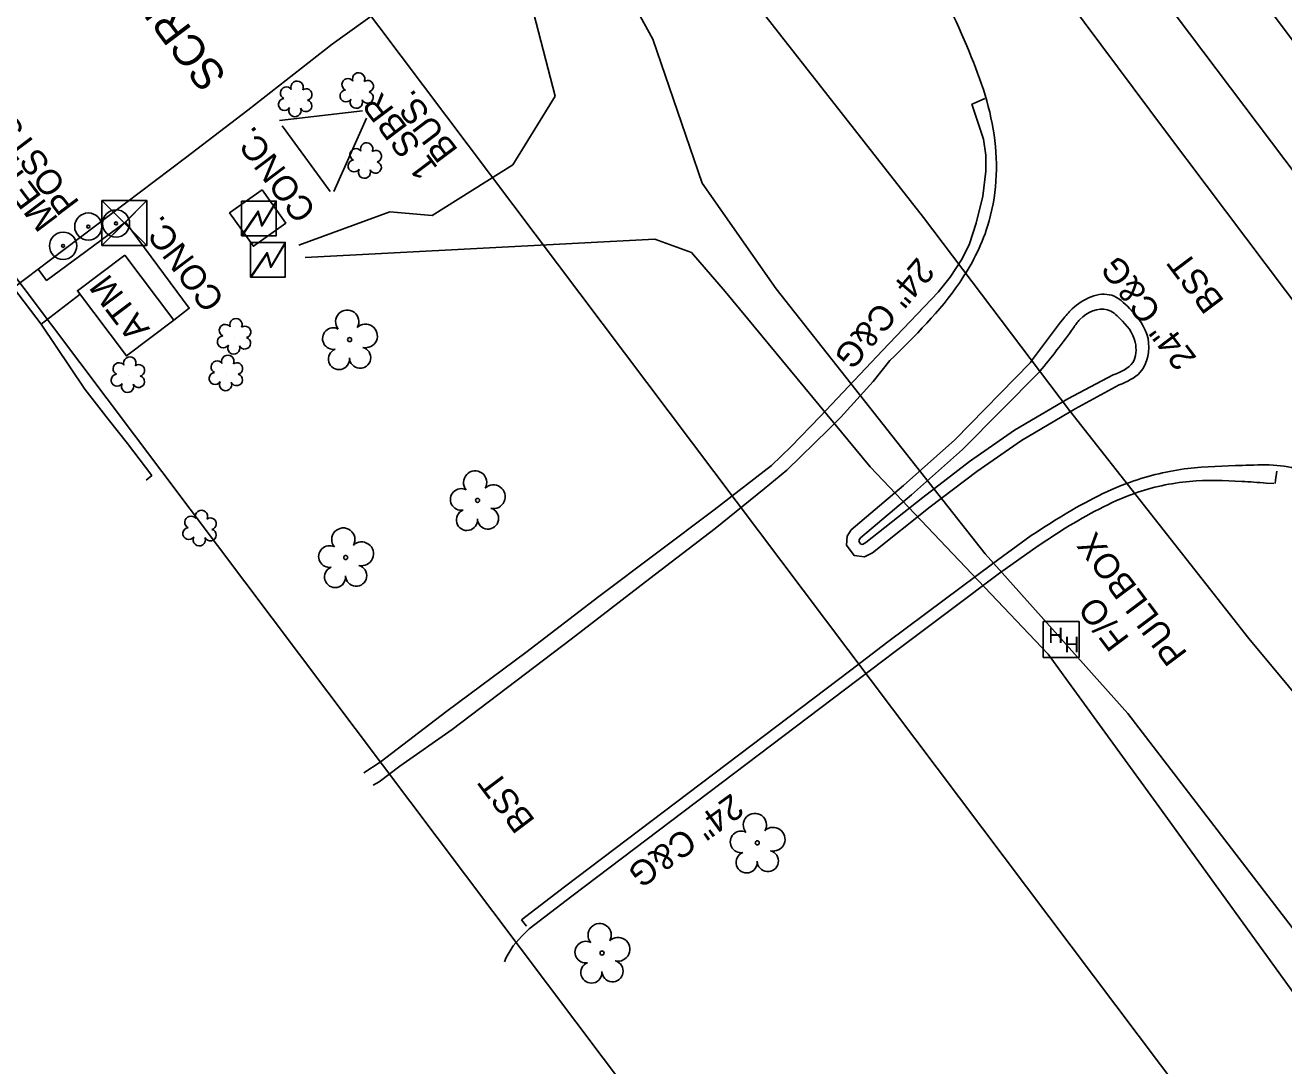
# Model space of a CAD drawing. Extents: x 1262092 to 1264624, y 774970 to 778314.
# Drawn here: x 1263925.8 to 1264127.3, y 775381.8 to 775548.3 of the extents above; entities that cross this region are included whole.
import ezdxf

# ---------------------------------------------------------------- set-up
doc = ezdxf.new("R2010")
doc.units = 0
for name, color, linetype in [('COGO Default Parcel', 7, 'Continuous'), ('CTL Vertical Benchmark CELL', 7, 'Continuous'), ('Exist Horizontal Alignment', 7, 'Continuous'), ('Exist Horizontal Alignment Station Label', 7, 'Continuous'), ('Exist Horizontal Alignment Tick Large', 7, 'Continuous'), ('Exist Horizontal Alignment Tick Small', 7, 'Continuous'), ('Exist Right of Way Line', 7, 'Continuous'), ('Exist Roads Curbs', 7, 'Continuous'), ('Exist Roads EOP', 7, 'Continuous'), ('Exist Roads EOP Other', 7, 'Continuous'), ('Exist Roads EOT', 7, 'Continuous'), ('Exist Structure Minor Drop Inlet Top Elevation', 7, 'Continuous'), ('Exist Utilities Power UG Cable SUE LOS B', 7, 'Continuous'), ('Exist Utilities Telephone Hand Hole CELL', 7, 'Continuous'), ('Exist Utilities Telephone Hand Hole Text', 7, 'Continuous'), ('Exist Utilities Telephone UG FO SUE LOS B', 7, 'Continuous'), ('Exist Utilities Water UG Line SUE LOS B', 7, 'Continuous'), ('Prop Horizontal Alignment', 7, 'Continuous'), ('Prop Horizontal Alignment Direction Label', 7, 'Continuous'), ('Prop Horizontal Alignment Station Label', 7, 'Continuous'), ('Prop Paved Shoulder', 7, 'Continuous'), ('Prop Superelevation Label', 7, 'Continuous'), ('Prop Terminator CELL', 7, 'Continuous'), ('Sheet Block Revision CELL', 7, 'Continuous'), ('Sheet Data Field CELL', 7, 'Continuous'), ('Sheet North Arrow Point CELL', 7, 'Continuous'), ('Sheet Plan CELL', 7, 'Continuous'), ('Sheet Sticker Incomplete CELL', 7, 'Continuous')]:
    doc.layers.add(name, color=color, linetype=linetype)

# ---------------------------------------------------------------- blocks, each defined once
blk = doc.blocks.new('CTL VERTICAL BENCHMARK')
at = {"layer": 'CTL Vertical Benchmark CELL'}
blk.add_line((0, 0), (0, 0), dxfattribs=at)
blk.add_lwpolyline([(-0.072, 0.07175), (0.07175, 0.07175), (0.07175, -0.072), (-0.072, -0.072)], close=True, dxfattribs=at)
for points in [[(0.07175, 0.07175), (-0.072, -0.072), (-0.000125, -0.000125), (0.07175, -0.072), (-0.072, 0.07175)], [(-0.000125, -0.000125), (0.07175, 0.07175), (-0.072, 0.07175), (-0.000125, -0.000125)], [(-0.000125, -0.000125), (-0.072, -0.072), (0.07175, -0.072), (-0.000125, -0.000125)]]:
    blk.add_lwpolyline(points, dxfattribs=at)

msp = doc.modelspace()

# ---------------------------------------------------------------- linework, layer by layer
at = {"layer": 'COGO Default Parcel'}
msp.add_line((1264304.64, 775002.74), (1263276.19, 776368.79), dxfattribs=at)
at = {"layer": 'Exist Horizontal Alignment'}
msp.add_line((1264460.35, 775084.79), (1262255.05, 778012.66), dxfattribs=at)
at = {"layer": 'Exist Horizontal Alignment Station Label'}
for p, q in [((1263966.49, 775533.11), (1263979.78, 775534.65)), ((1263980.41, 775533.49), (1263975.17, 775521.71)), ((1263974.62, 775521.75), (1263966.94, 775532.21))]:
    msp.add_line(p, q, dxfattribs=at)
at = {"layer": 'Exist Horizontal Alignment Tick Large'}
for p, q in [((1263978.93, 775537.71), (1263978.93, 775537.71)), ((1263969.08, 775536.37), (1263969.08, 775536.37)), ((1263980.22, 775526.51), (1263980.22, 775526.51)), ((1263959.29, 775498.37), (1263959.29, 775498.37)), ((1263942.29, 775492.22), (1263942.29, 775492.22)), ((1263957.98, 775492.51), (1263957.98, 775492.51)), ((1263953.77, 775467.68), (1263953.77, 775467.68))]:
    msp.add_line(p, q, dxfattribs=at)
for centre, radius, start, end in [((1263969.31, 775538.41), 0.99, 334.8391, 200.4717), ((1263977.45, 775538.84), 0.968, 35.8908, 245.4216), ((1263979.16, 775539.75), 0.99, 334.8391, 200.4717), ((1263980.6, 775538.58), 0.929, 284.4567, 126.0861), ((1263967.6, 775537.49), 0.968, 35.8908, 245.4216), ((1263970.75, 775537.24), 0.929, 284.4567, 126.0861), ((1263977.13, 775537.01), 0.955, 95.1099, 327.9534), ((1263980.57, 775536.78), 0.937, 204.9913, 73.4601), ((1263967.28, 775535.66), 0.955, 95.1099, 327.9534), ((1263968.95, 775534.68), 0.984, 151.2797, 21.387), ((1263970.72, 775535.44), 0.937, 204.9913, 73.4601), ((1263978.8, 775536.03), 0.984, 151.2797, 21.387), ((1263980.45, 775528.55), 0.99, 334.8391, 200.4717), ((1263978.74, 775527.64), 0.968, 35.8908, 245.4216), ((1263981.89, 775527.38), 0.929, 284.4567, 126.0861), ((1263978.42, 775525.81), 0.955, 95.1099, 327.9534), ((1263980.09, 775524.83), 0.984, 151.2797, 21.387), ((1263981.86, 775525.58), 0.937, 204.9913, 73.4601), ((1263959.52, 775500.41), 0.99, 334.8391, 200.4717), ((1263957.81, 775499.49), 0.968, 35.8908, 245.4216), ((1263960.97, 775499.24), 0.929, 284.4567, 126.0861), ((1263957.49, 775497.66), 0.955, 95.1099, 327.9534), ((1263959.17, 775496.68), 0.984, 151.2797, 21.387), ((1263960.93, 775497.44), 0.937, 204.9913, 73.4601), ((1263942.52, 775494.27), 0.99, 334.8391, 200.4717), ((1263956.5, 775493.64), 0.968, 35.8908, 245.4216), ((1263958.21, 775494.55), 0.99, 334.8391, 200.4717), ((1263940.81, 775493.35), 0.968, 35.8908, 245.4216), ((1263943.96, 775493.09), 0.929, 284.4567, 126.0861), ((1263956.18, 775491.81), 0.955, 95.1099, 327.9534), ((1263959.65, 775493.38), 0.929, 284.4567, 126.0861), ((1263940.49, 775491.52), 0.955, 95.1099, 327.9534), ((1263942.16, 775490.54), 0.984, 151.2797, 21.387), ((1263943.93, 775491.3), 0.937, 204.9913, 73.4601), ((1263957.85, 775490.83), 0.984, 151.2797, 21.387), ((1263959.62, 775491.58), 0.937, 204.9913, 73.4601), ((1263954, 775469.72), 0.99, 334.8391, 200.4717), ((1263952.29, 775468.8), 0.968, 35.8908, 245.4216), ((1263955.44, 775468.55), 0.929, 284.4567, 126.0861), ((1263951.97, 775466.97), 0.955, 95.1099, 327.9534), ((1263953.64, 775465.99), 0.984, 151.2797, 21.387), ((1263955.41, 775466.75), 0.937, 204.9913, 73.4601)]:
    msp.add_arc(centre, radius, start, end, dxfattribs=at)
at = {"layer": 'Exist Horizontal Alignment Tick Small'}
for p, q in [((1263977.71, 775498.03), (1263977.71, 775498.03)), ((1263998.2, 775472.29), (1263998.2, 775472.29)), ((1263977.09, 775463.15), (1263977.09, 775463.15)), ((1264042.98, 775417.48), (1264042.98, 775417.48)), ((1264018.14, 775399.84), (1264018.14, 775399.84))]:
    msp.add_line(p, q, dxfattribs=at)
for centre in [(1263977.71, 775498.03), (1263998.2, 775472.29), (1263977.09, 775463.15), (1264042.98, 775417.48), (1264018.14, 775399.84)]:
    msp.add_circle(centre, 0.326, dxfattribs=at)
for centre, radius, start, end in [((1263977.33, 775500.9), 1.86, 330.1651, 219.7134), ((1263975.11, 775498.18), 1.73, 62.6636, 279.3457), ((1263980.26, 775498.62), 1.9, 257.1011, 134.1999), ((1263979.39, 775495.13), 1.7, 181.2822, 74.56), ((1263976.01, 775494.91), 1.69, 111.5671, 6.231), ((1263997.81, 775475.16), 1.86, 330.1651, 219.7134), ((1264000.74, 775472.87), 1.9, 257.1011, 134.1999), ((1263995.59, 775472.44), 1.73, 62.6636, 279.3457), ((1263996.49, 775469.16), 1.69, 111.5671, 6.231), ((1263999.87, 775469.39), 1.7, 181.2822, 74.56), ((1263976.71, 775466.02), 1.86, 330.1651, 219.7134), ((1263974.49, 775463.3), 1.73, 62.6636, 279.3457), ((1263979.64, 775463.74), 1.9, 257.1011, 134.1999), ((1263975.39, 775460.03), 1.69, 111.5671, 6.231), ((1263978.76, 775460.25), 1.7, 181.2822, 74.56), ((1264042.6, 775420.35), 1.86, 330.1651, 219.7134), ((1264040.38, 775417.63), 1.73, 62.6636, 279.3457), ((1264045.53, 775418.07), 1.9, 257.1011, 134.1999), ((1264044.66, 775414.58), 1.7, 181.2822, 74.56), ((1264041.28, 775414.36), 1.69, 111.5671, 6.231), ((1264017.75, 775402.71), 1.86, 330.1651, 219.7134), ((1264020.68, 775400.43), 1.9, 257.1011, 134.1999), ((1264015.53, 775399.99), 1.73, 62.6636, 279.3457), ((1264016.43, 775396.72), 1.69, 111.5671, 6.231), ((1264019.81, 775396.94), 1.7, 181.2822, 74.56)]:
    msp.add_arc(centre, radius, start, end, dxfattribs=at)
at = {"layer": 'Exist Right of Way Line'}
msp.add_line((1263350.65, 776386.89), (1264378.08, 775022.83), dxfattribs=at)
at = {"layer": 'Exist Roads Curbs'}
for p, q in [((1264075.85, 775480.41), (1264088.19, 775492.89)), ((1264124.44, 775475.07), (1264125.67, 775474.98)), ((1264087.96, 775465.02), (1264092.3, 775467.87))]:
    msp.add_line(p, q, dxfattribs=at)
for points in [[(1263929.83, 775510.81), (1263951.43, 775527.14), (1263961.43, 775534.75), (1263974.94, 775545.29), (1263991.17, 775556.97), (1263992.1, 775557.91), (1263993.17, 775559.5), (1263993.88, 775561.08), (1263993.92, 775562.94), (1263993.74, 775563.88), (1263992.67, 775565.7), (1263979.96, 775582.39), (1263961.18, 775607.01), (1263951.7, 775619.64), (1263934.23, 775642.68), (1263922.89, 775657.73), (1263909.11, 775675.95)], [(1263980, 775428.71), (1263982.62, 775430.39), (1263993.3, 775438.55), (1264005.91, 775447.94), (1264017.62, 775456.9), (1264036.08, 775470.79), (1264045.26, 775477.89), (1264048.33, 775480.88), (1264053.08, 775485.79), (1264063.03, 775496.26), (1264071.96, 775505.62), (1264073.87, 775508.03), (1264075.79, 775510.96), (1264076.94, 775513.33), (1264078.04, 775516.67), (1264079.08, 775520.97), (1264079.58, 775524.96), (1264079.55, 775527.56), (1264079.19, 775530.09), (1264077.35, 775535.73)], [(1264077.35, 775535.73), (1264077.35, 775535.73)], [(1264099.96, 775492.37), (1264092.68, 775488.53), (1264084.14, 775483.55), (1264076.98, 775478.52)], [(1264076.98, 775478.52), (1264069.47, 775472.77), (1264060.37, 775465.54), (1264059.82, 775465.24), (1264059.57, 775465.28), (1264059.27, 775465.68), (1264059.29, 775465.96), (1264059.49, 775466.29), (1264067.65, 775473.2), (1264075.85, 775480.41)], [(1264087.96, 775465.02), (1264081.76, 775460.62), (1264074.03, 775454.83), (1264065.04, 775448.1), (1264059.11, 775443.62), (1264013.27, 775408.94), (1264006.48, 775403.71), (1264005.25, 775402.49), (1264003.9, 775400.98), (1264002.78, 775399.14), (1264002.52, 775398.43)]]:
    msp.add_lwpolyline(points, dxfattribs=at)
for points in [[(1264088.19, 775492.89), (1264093.6, 775499.91), (1264094.64, 775501.25), (1264099.04, 775502.78), (1264101.05, 775501.41), (1264103.49, 775497.62), (1264103.12, 775494.37), (1264099.96, 775492.37)], [(1264092.3, 775467.87), (1264103.37, 775473.41), (1264112.2, 775475.32), (1264120.56, 775475.33), (1264124.44, 775475.07)]]:
    msp.add_spline(points, degree=3, dxfattribs=at)
at = {"layer": 'Exist Roads EOP'}
msp.add_line((1264074.62, 775481.99), (1264086.72, 775494.38), dxfattribs=at)
msp.add_lwpolyline([(1264100.92, 775490.76), (1264093.88, 775486.95), (1264085.29, 775481.89), (1264078.15, 775476.91)], dxfattribs=at)
for points in [[(1264042.88, 775595.85), (1264069, 775560.24), (1264076.53, 775545.02), (1264080.9, 775530.78), (1264079.85, 775516.16), (1264075.39, 775507.17), (1264064.21, 775494.66)], [(1264086.72, 775494.38), (1264091.87, 775501.21), (1264093.42, 775502.97), (1264099.73, 775505.11), (1264102.56, 775503.02), (1264105.54, 775498.19), (1264104.28, 775492.8), (1264100.92, 775490.76)], [(1264086.81, 775466.65), (1264091.31, 775469.51), (1264102.73, 775475.22), (1264111.91, 775477.39), (1264120.66, 775477.89), (1264130.22, 775477.03), (1264134.8, 775474.26), (1264138.29, 775471.59), (1264165.32, 775437.52)]]:
    msp.add_spline(points, degree=3, dxfattribs=at)
at = {"layer": 'Exist Roads EOP Other'}
msp.add_line((1264006.03, 775404.17), (1264005.22, 775405.15), dxfattribs=at)
for points in [[(1264077.35, 775535.73), (1264077.86, 775535.94), (1264079.42, 775536.59)], [(1263923.89, 775506.29), (1263927.85, 775509.3), (1263929.83, 775510.81)], [(1263923.89, 775506.29), (1263928.32, 775500.52), (1263935.31, 775490.08), (1263939.07, 775485.29), (1263942.13, 775481.39), (1263946.04, 775476.3), (1263945.16, 775475.53)], [(1264064.21, 775494.66), (1264061.53, 775491.32), (1264056.36, 775485.61), (1264054.41, 775483.62), (1264047.74, 775477.13), (1264044.1, 775474.16), (1264036.22, 775467.79), (1264025.77, 775459.8), (1264013.21, 775450.09), (1263994.16, 775435.64), (1263985.75, 775429.75), (1263982.46, 775427.26), (1263981.49, 775426.69)], [(1264078.15, 775476.91), (1264070.65, 775471.24), (1264061.44, 775463.91), (1264060.16, 775463.23), (1264058.48, 775463.49), (1264057.29, 775465.12), (1264057.4, 775466.57), (1264058, 775467.56), (1264066.38, 775474.67), (1264074.62, 775481.99)], [(1264125.88, 775474.97), (1264125.96, 775475.53), (1264126.17, 775476.98)], [(1264086.81, 775466.65), (1264080.63, 775462.16), (1264072.89, 775456.35), (1264063.89, 775449.63), (1264057.96, 775445.14), (1264012.12, 775410.45), (1264005.22, 775405.15)]]:
    msp.add_lwpolyline(points, dxfattribs=at)
at = {"layer": 'Exist Roads EOT'}
for points in [[(1264446.09, 775083.45), (1264419.18, 775119.01), (1264392.54, 775154.06), (1264369.93, 775183.78), (1264343.71, 775218.57), (1264317, 775253.46), (1264292.67, 775285.65), (1264265.72, 775321.45), (1264237.79, 775358.61), (1264211.14, 775394.4), (1264184.66, 775429.54), (1264159.42, 775463.25), (1264133.92, 775497.47), (1264108.52, 775531.19), (1264082.14, 775566.55), (1264057.31, 775599.4), (1264024.24, 775643.38), (1263996.61, 775679.88), (1263968.79, 775716.67), (1263941.99, 775752.17)], [(1263986.52, 775734.29), (1264013.59, 775698.59), (1264042.53, 775660.51), (1264070.23, 775623.69), (1264096.97, 775588.25), (1264125.47, 775550.21), (1264152.28, 775514.35), (1264177.51, 775480.42), (1264205.19, 775443.24), (1264206.48, 775441.72)]]:
    msp.add_lwpolyline(points, dxfattribs=at)
at = {"layer": 'Exist Utilities Power UG Cable SUE LOS B'}
for points in [[(1263969.57, 775513.14), (1263984.13, 775518.47), (1263990.91, 775517.89), (1264003.85, 775526.02), (1264010.62, 775536.96), (1264003.82, 775563.37), (1263976.28, 775599.38), (1263948.69, 775636.38), (1263920.39, 775671.17), (1263887.51, 775714.06), (1263887.5, 775714.1), (1263859.69, 775750.28), (1263825.01, 775796.28), (1263790.77, 775842.97), (1263768.46, 775865)], [(1264395.36, 775040.74), (1264370.8, 775076.36), (1264340.19, 775112.15), (1264308.39, 775149.99), (1264277.8, 775188.45), (1264254.82, 775218.46), (1264230.51, 775255.61), (1264208, 775290.17), (1264185.34, 775318.09), (1264158.04, 775354.59), (1264133.61, 775386.92), (1264107.25, 775423.32), (1264089.56, 775447.66), (1264061.08, 775477.65), (1264037.85, 775505.73), (1264032.45, 775511.96), (1264026.57, 775514.09), (1263970.61, 775511.19)]]:
    msp.add_lwpolyline(points, dxfattribs=at)
at = {"layer": 'Exist Utilities Telephone Hand Hole CELL'}
for p, q in [((1264088.77, 775452.89), (1264088.77, 775447.17)), ((1264094.5, 775452.89), (1264088.77, 775452.89)), ((1264094.5, 775447.17), (1264094.5, 775452.89)), ((1264091.64, 775450.03), (1264091.64, 775450.03)), ((1264088.77, 775447.17), (1264094.5, 775447.17))]:
    msp.add_line(p, q, dxfattribs=at)
at = {"layer": 'Exist Utilities Telephone UG FO SUE LOS B'}
msp.add_lwpolyline([(1264412.43, 775054.27), (1264383.09, 775084.33), (1264350.27, 775127.37), (1264319.47, 775167.42), (1264288.52, 775206.2), (1264253.33, 775248.38), (1264233.02, 775276.08), (1264197.49, 775318.53), (1264165.2, 775359.15), (1264131.6, 775400.04), (1264102.3, 775438.18), (1264079.45, 775463.73), (1264046.01, 775506.17), (1264034.16, 775523.07), (1264026.26, 775546.1), (1264015.26, 775566.11), (1263989.3, 775607.52), (1263955.25, 775658.94), (1263921.26, 775710.27), (1263888.91, 775754.45), (1263860.31, 775793.96), (1263832.43, 775832.72), (1263818.26, 775866.25), (1263816.28, 775877)], dxfattribs=at)
at = {"layer": 'Exist Utilities Water UG Line SUE LOS B'}
msp.add_lwpolyline([(1264262.47, 775052.4), (1264270.03, 775057.49), (1264308.25, 775083.86), (1264311.99, 775091.01), (1264333.07, 775106.94), (1264365.39, 775127.89), (1264356.78, 775138.68), (1264342.07, 775157.58), (1264315.02, 775194.18), (1264289.27, 775228.94), (1264261.35, 775265.49), (1264234.66, 775298.88), (1264204.95, 775340.41), (1264179.39, 775376.51), (1264153.98, 775411.4), (1264121.66, 775450.17), (1264092.98, 775486.7), (1264069.57, 775517.58), (1264043.23, 775551.19), (1264018.68, 775582.59), (1263995.06, 775614.62), (1263975.68, 775643.74), (1263951.8, 775677.27), (1263925.33, 775714.09)], dxfattribs=at)
at = {"layer": 'Prop Horizontal Alignment Direction Label'}
msp.add_lwpolyline([(1263941.72, 775511.54), (1263949.56, 775501.11), (1263941.98, 775495.41), (1263934.14, 775505.84)], close=True, dxfattribs=at)
at = {"layer": 'Prop Horizontal Alignment Station Label'}
for centre, radius in [((1263940.32, 775516.61), 2.18), ((1263935.88, 775516.11), 2.18), ((1263940.32, 775516.61), 0.24), ((1263931.84, 775513.03), 2.18), ((1263935.88, 775516.11), 0.24), ((1263931.84, 775513.03), 0.24)]:
    msp.add_circle(centre, radius, dxfattribs=at)
at = {"layer": 'Prop Superelevation Label'}
msp.add_line((1263928.32, 775500.52), (1263934.57, 775505.27), dxfattribs=at)
msp.add_lwpolyline([(1263963.69, 775522.01), (1263967.5, 775516.67), (1263962.31, 775512.96), (1263958.49, 775518.3)], close=True, dxfattribs=at)
msp.add_lwpolyline([(1263927.85, 775509.3), (1263929.21, 775507.49), (1263935.49, 775512.15), (1263941.83, 775516.83), (1263952.05, 775503.05), (1263949.56, 775501.11)], dxfattribs=at)
at = {"layer": 'Sheet North Arrow Point CELL'}
for p, q in [((1263963.26, 775517.58), (1263963.26, 775517.58)), ((1263964.71, 775510.96), (1263964.71, 775510.96))]:
    msp.add_line(p, q, dxfattribs=at)
for points in [[(1263960.42, 775520.19), (1263965.97, 775520.19), (1263965.97, 775514.64), (1263960.42, 775514.64)], [(1263961.87, 775513.57), (1263967.42, 775513.57), (1263967.42, 775508.02), (1263961.87, 775508.02)]]:
    msp.add_lwpolyline(points, close=True, dxfattribs=at)
for points in [[(1263960.42, 775514.64), (1263963.06, 775518.58), (1263963.69, 775516.37), (1263965.97, 775520.19)], [(1263960.49, 775514.64), (1263963.06, 775518.37), (1263963.65, 775516.19), (1263965.97, 775520.04)], [(1263961.87, 775508.02), (1263964.51, 775511.96), (1263965.14, 775509.75), (1263967.42, 775513.57)], [(1263961.94, 775508.02), (1263964.51, 775511.75), (1263965.1, 775509.57), (1263967.42, 775513.42)]]:
    msp.add_lwpolyline(points, dxfattribs=at)

# ---------------------------------------------------------------- block references
at = {"layer": 'CTL Vertical Benchmark CELL', "xscale": 50, "yscale": 50}
msp.add_blockref('CTL VERTICAL BENCHMARK', (1263941.67, 775516.69), dxfattribs=at)
msp.add_blockref('CTL VERTICAL BENCHMARK', (1263941.67, 775516.69), dxfattribs=at)
msp.add_blockref('CTL VERTICAL BENCHMARK', (1263941.67, 775516.69), dxfattribs=at)

# ---------------------------------------------------------------- texts
at = {"layer": 'Exist Structure Minor Drop Inlet Top Elevation'}
msp.add_text("TOP=1198.99'", height=4, rotation=126.9874, dxfattribs=at).set_placement((1264148.65, 775540.09))
at = {"layer": 'Exist Utilities Telephone Hand Hole CELL'}
for p in [(1264089.55, 775449.44), (1264092.12, 775447.97)]:
    msp.add_text('H', height=2.5, dxfattribs=at).set_placement(p)
at = {"layer": 'Exist Utilities Telephone Hand Hole Text'}
for s, p in [('PULLBOX', (1264111.97, 775447.78)), ('F/O', (1264102.69, 775450.13))]:
    msp.add_text(s, height=4, rotation=126.9746, dxfattribs=at).set_placement(p)
at = {"layer": 'Prop Horizontal Alignment'}
for p in [(1264117.88, 775504.19), (1264007.54, 775421.04)]:
    msp.add_text('BST', height=4, rotation=126.9874, dxfattribs=at).set_placement(p)
at = {"layer": 'Prop Paved Shoulder'}
for s, p in [('1 SBR', (1263991.97, 775525.52)), ('BUS.', (1263995.2, 775528.35))]:
    msp.add_text(s, height=4, rotation=126.9874, dxfattribs=at).set_placement(p)
at = {"layer": 'Prop Terminator CELL'}
msp.add_text('SCRIBE IN CONC. PAD AT "CASH POINTS"', height=5, rotation=126.9874, dxfattribs=at).set_placement((1263958.19, 775540.26))
at = {"layer": 'Sheet Block Revision CELL'}
msp.add_text('ATM', height=4, rotation=126.9874, dxfattribs=at).set_placement((1263945.83, 775499.73))
at = {"layer": 'Sheet Data Field CELL'}
for p in [(1263972.53, 775518.71), (1263957.87, 775504.44)]:
    msp.add_text('CONC.', height=4, rotation=126.9874, dxfattribs=at).set_placement(p)
at = {"layer": 'Sheet Plan CELL'}
for s, p in [('POSTS', (1263934.58, 775519.95)), ('METAL ', (1263931.2, 775517.32))]:
    msp.add_text(s, height=4, rotation=126.9874, dxfattribs=at).set_placement(p)
at = {"layer": 'Sheet Sticker Incomplete CELL'}
for rotation, p in [(229.4651, (1264068.65, 775511.39)), (126.9746, (1264113.44, 775495.09)), (215.9381, (1264038.88, 775425.53))]:
    msp.add_text('24" C&G', height=4, rotation=rotation, dxfattribs=at).set_placement(p)

doc.saveas('drawing.dxf')
